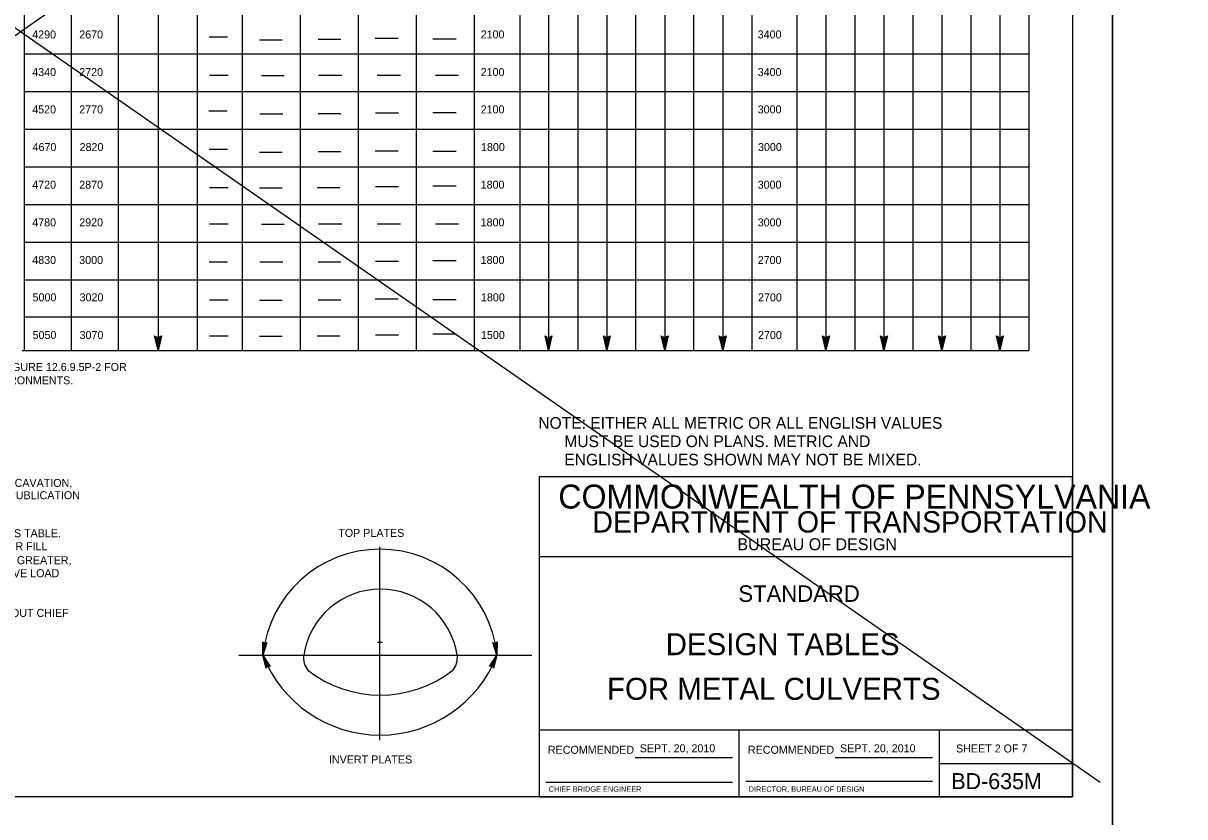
# Model space of a CAD drawing. Extents: x 591 to 2288, y -189 to 2187.
# Drawn here: x 1024 to 1459.5, y 1006.7 to 1304.4 of the extents above; entities that cross this region are included whole.
import ezdxf

# ---------------------------------------------------------------- set-up
doc = ezdxf.new("R2010")
doc.units = 0
for name, color, linetype in [('1', 7, 'Continuous'), ('2', 7, 'Continuous'), ('PLT-BNDY', 7, 'Continuous')]:
    doc.layers.add(name, color=color, linetype=linetype)

msp = doc.modelspace()

# ---------------------------------------------------------------- linework, layer by layer
at = {"layer": '1'}
for p, q in [((623.13, 1579.43), (1427.79, 1019.69)), ((1414.15, 1574.88), (614.04, 1015.14)), ((1292.34, 1014.21), (1292.34, 1039.21)), ((1367.34, 1039.21), (1367.34, 1014.21)), ((1253.43, 1028.93), (1289.84, 1028.93)), ((1328.43, 1028.93), (1364.84, 1028.93)), ((1219.84, 1019.71), (1289.84, 1019.71)), ((1294.84, 1020.09), (1364.84, 1020.09))]:
    msp.add_line(p, q, dxfattribs=at)
at = {"layer": '2'}
for p, q in [((1417.34, 1578.21), (1417.34, 1014.21)), ((1024.34, 1485.59), (1024.34, 1181.59)), ((1059.59, 1485.59), (1059.59, 1181.59)), ((1089.21, 1485.59), (1089.21, 1181.59)), ((1400.96, 1485.59), (1400.96, 1181.59)), ((1193.09, 1473.84), (1193.09, 1181.59)), ((1297.09, 1473.84), (1297.09, 1181.59)), ((1106.09, 1462.21), (1106.09, 1181.59)), ((1210.09, 1462.21), (1210.09, 1181.59)), ((1313.96, 1462.21), (1313.96, 1181.59)), ((1149.59, 1452.34), (1149.59, 1181.59)), ((1253.46, 1452.34), (1253.46, 1181.59)), ((1357.46, 1452.34), (1357.46, 1181.59)), ((1127.84, 1438.21), (1127.84, 1181.59)), ((1171.34, 1438.21), (1171.34, 1181.59)), ((1231.84, 1438.21), (1231.84, 1181.59)), ((1275.21, 1438.21), (1275.21, 1181.59)), ((1335.71, 1438.21), (1335.71, 1181.59)), ((1379.21, 1438.21), (1379.21, 1181.59)), ((1041.96, 1435.46), (1041.96, 1181.59)), ((1074.59, 1408.71), (1074.59, 1181.59)), ((1220.84, 1408.71), (1220.84, 1181.59)), ((1242.71, 1408.71), (1242.71, 1181.59)), ((1264.46, 1408.71), (1264.46, 1181.59)), ((1286.21, 1408.71), (1286.21, 1181.59)), ((1324.84, 1408.71), (1324.84, 1181.59)), ((1346.59, 1408.71), (1346.59, 1181.59)), ((1368.34, 1408.71), (1368.34, 1181.59)), ((1390.09, 1408.71), (1390.09, 1181.59)), ((1093.71, 1299.34), (1100.59, 1299.34)), ((1112.59, 1298.21), (1121.09, 1298.21)), ((1134.59, 1298.46), (1143.09, 1298.46)), ((1155.96, 1298.84), (1164.59, 1298.84)), ((1177.59, 1298.59), (1186.34, 1298.59)), ((1024.34, 1292.96), (1400.96, 1292.96)), ((1093.84, 1284.96), (1100.84, 1284.96)), ((1113.34, 1284.84), (1121.84, 1284.84)), ((1134.71, 1284.96), (1143.46, 1284.96)), ((1156.71, 1284.96), (1165.46, 1284.96)), ((1178.59, 1284.96), (1187.21, 1284.96)), ((1024.34, 1278.84), (1400.96, 1278.84)), ((1093.59, 1271.59), (1100.46, 1271.59)), ((1112.71, 1270.46), (1121.34, 1270.46)), ((1134.59, 1270.59), (1143.09, 1270.59)), ((1156.09, 1270.84), (1164.71, 1270.84)), ((1177.59, 1270.96), (1186.34, 1270.96)), ((1024.34, 1264.71), (1400.96, 1264.71)), ((1093.71, 1257.21), (1100.59, 1257.21)), ((1112.59, 1256.09), (1121.09, 1256.09)), ((1134.59, 1256.34), (1143.09, 1256.34)), ((1155.96, 1256.59), (1164.59, 1256.59)), ((1177.59, 1256.46), (1186.34, 1256.46)), ((1024.34, 1250.59), (1400.96, 1250.59)), ((1093.84, 1242.84), (1100.84, 1242.84)), ((1112.59, 1242.71), (1121.09, 1242.71)), ((1134.21, 1242.84), (1142.71, 1242.84)), ((1156.09, 1243.21), (1164.71, 1243.21)), ((1177.59, 1243.46), (1186.34, 1243.46)), ((1024.34, 1236.46), (1400.96, 1236.46)), ((1093.84, 1229.21), (1100.84, 1229.21)), ((1113.34, 1229.09), (1121.84, 1229.09)), ((1134.71, 1229.21), (1143.46, 1229.21)), ((1156.71, 1229.21), (1165.46, 1229.21)), ((1178.59, 1229.21), (1187.21, 1229.21)), ((1024.34, 1222.34), (1400.96, 1222.34)), ((1156.09, 1215.09), (1164.71, 1215.09)), ((1177.59, 1215.34), (1186.34, 1215.34)), ((1093.71, 1214.96), (1100.59, 1214.96)), ((1112.71, 1214.84), (1121.34, 1214.84)), ((1134.59, 1214.96), (1143.09, 1214.96)), ((1024.34, 1208.21), (1400.96, 1208.21)), ((1093.84, 1200.59), (1100.84, 1200.59)), ((1112.59, 1200.46), (1121.09, 1200.46)), ((1134.59, 1200.59), (1143.09, 1200.59)), ((1155.96, 1200.96), (1164.59, 1200.96)), ((1177.59, 1200.71), (1186.34, 1200.71)), ((1024.34, 1194.21), (1400.96, 1194.21)), ((1093.84, 1187.09), (1100.84, 1187.09)), ((1112.59, 1186.96), (1121.09, 1186.96)), ((1134.21, 1187.09), (1142.71, 1187.09)), ((1156.09, 1187.46), (1164.71, 1187.46)), ((1177.59, 1187.84), (1186.34, 1187.84)), ((1023.59, 1181.59), (1400.96, 1181.59)), ((1417.34, 1134.21), (1217.34, 1134.21)), ((1217.34, 1134.21), (1217.34, 1014.21)), ((1417.34, 1014.21), (1417.34, 1134.21)), ((1157.71, 1035.46), (1157.71, 1107.96)), ((1417.34, 1104.21), (1217.34, 1104.21)), ((1156.84, 1072.21), (1158.59, 1072.21)), ((1104.84, 1067.34), (1214.71, 1067.34)), ((1185.09, 1061.71), (1184.96, 1061.71)), ((1417.34, 1039.21), (1217.34, 1039.21)), ((1367.34, 1026.71), (1417.34, 1026.71)), ((1417.34, 1014.21), (631.34, 1014.21)), ((1217.34, 1014.21), (1417.34, 1014.21))]:
    msp.add_line(p, q, dxfattribs=at)
for points in [[(1075.46, 1186.84), (1074.96, 1186.59), (1074.59, 1181.59), (1075.46, 1186.84), (1075.84, 1187.09), (1074.59, 1181.59), (1074.21, 1186.59), (1073.59, 1186.71), (1074.59, 1181.59), (1073.21, 1187.09), (1073.59, 1186.71)], [(1221.96, 1186.84), (1221.34, 1186.59), (1220.84, 1181.59), (1221.96, 1186.84), (1222.21, 1187.09), (1220.84, 1181.59), (1220.46, 1186.59), (1220.09, 1186.71), (1220.84, 1181.59), (1219.71, 1187.09), (1220.09, 1186.71)], [(1243.71, 1186.84), (1243.09, 1186.59), (1242.71, 1181.59), (1243.71, 1186.84), (1243.96, 1187.09), (1242.71, 1181.59), (1242.34, 1186.59), (1241.71, 1186.71), (1242.71, 1181.59), (1241.46, 1187.09), (1241.71, 1186.71)], [(1265.34, 1186.84), (1264.84, 1186.59), (1264.46, 1181.59), (1265.34, 1186.84), (1265.71, 1187.09), (1264.46, 1181.59), (1264.09, 1186.59), (1263.46, 1186.71), (1264.46, 1181.59), (1263.09, 1187.09), (1263.46, 1186.71)], [(1287.09, 1186.84), (1286.59, 1186.59), (1286.21, 1181.59), (1287.09, 1186.84), (1287.46, 1187.09), (1286.21, 1181.59), (1285.84, 1186.59), (1285.21, 1186.71), (1286.21, 1181.59), (1284.84, 1187.09), (1285.21, 1186.71)], [(1325.84, 1186.84), (1325.21, 1186.59), (1324.84, 1181.59), (1325.84, 1186.84), (1326.21, 1187.09), (1324.84, 1181.59), (1324.46, 1186.59), (1323.96, 1186.71), (1324.84, 1181.59), (1323.59, 1187.09), (1323.96, 1186.71)], [(1347.59, 1186.84), (1346.96, 1186.59), (1346.59, 1181.59), (1347.59, 1186.84), (1347.96, 1187.09), (1346.59, 1181.59), (1346.21, 1186.59), (1345.71, 1186.71), (1346.59, 1181.59), (1345.34, 1187.09), (1345.71, 1186.71)], [(1369.34, 1186.84), (1368.71, 1186.59), (1368.34, 1181.59), (1369.34, 1186.84), (1369.71, 1187.09), (1368.34, 1181.59), (1367.96, 1186.59), (1367.34, 1186.71), (1368.34, 1181.59), (1367.09, 1187.09), (1367.34, 1186.71)], [(1391.09, 1186.84), (1390.59, 1186.59), (1390.09, 1181.59), (1391.09, 1186.84), (1391.34, 1187.09), (1390.09, 1181.59), (1389.71, 1186.59), (1389.09, 1186.71), (1390.09, 1181.59), (1388.84, 1187.09), (1389.09, 1186.71)], [(1115.09, 1071.84), (1114.71, 1071.71), (1113.84, 1067.34), (1115.09, 1071.84), (1115.34, 1072.09), (1113.84, 1067.34), (1114.34, 1071.84), (1113.96, 1072.09), (1113.84, 1067.34), (1113.84, 1072.34), (1113.96, 1072.09)], [(1201.46, 1072.09), (1201.21, 1071.84), (1201.59, 1067.34), (1201.46, 1072.09), (1201.71, 1072.34), (1201.59, 1067.34), (1200.71, 1071.71), (1200.34, 1071.84), (1201.59, 1067.34), (1200.09, 1072.09), (1200.34, 1071.84)], [(1115.21, 1062.84), (1115.46, 1063.09), (1113.84, 1067.34), (1115.21, 1062.84), (1115.09, 1062.46), (1113.84, 1067.34), (1115.84, 1063.34), (1116.21, 1063.21), (1113.84, 1067.34), (1116.59, 1063.09), (1116.21, 1063.21)], [(1199.09, 1063.21), (1199.46, 1063.34), (1201.59, 1067.34), (1199.09, 1063.21), (1198.84, 1063.09), (1201.59, 1067.34), (1199.96, 1063.09), (1200.21, 1062.84), (1201.59, 1067.34), (1200.34, 1062.46), (1200.21, 1062.84)]]:
    msp.add_lwpolyline(points, dxfattribs=at)
for centre, radius, start, end in [((1157.72, 1062.98), 44.11, 5.6241, 174.3759), ((1157.9, 1063.05), 29.07, 8.4323, 171.5893), ((1157.72, 1084.53), 47.16, 201.4219, 338.5781), ((1136.53, 1066.31), 7.46, 172.3667, 218.4979), ((1179.27, 1066.33), 7.46, 321.5021, 7.6333), ((1157.85, 1096.64), 44.27, 232.1732, 307.8489)]:
    msp.add_arc(centre, radius, start, end, dxfattribs=at)
at = {"layer": 'PLT-BNDY'}
for points in [[(591.34, 1593.21), (1432.34, 1593.21), (1432.34, 999.21), (591.34, 999.21)], [(1432.34, 1593.21), (2273.34, 1593.21), (2273.34, 999.21), (1432.34, 999.21)]]:
    msp.add_lwpolyline(points, close=True, dxfattribs=at)

# ---------------------------------------------------------------- texts
at = {"layer": '1'}
for s, height, p in [('RECOMMENDED', 3, (1220.67, 1030.34)), ('RECOMMENDED', 3, (1295.67, 1030.34)), ('CHIEF BRIDGE ENGINEER', 2.0003, (1220.93, 1016.09)), ('DIRECTOR, BUREAU OF DESIGN', 2.0003, (1295.94, 1016.09))]:
    msp.add_text(s, height=height, dxfattribs=at).set_placement(p)
at = {"layer": '2'}
for s, height, p in [('4290', 3, (1027.34, 1298.71)), ('2670', 3, (1044.96, 1298.71)), ('2100', 3, (1195.46, 1298.71)), ('3400', 3, (1299.34, 1298.71)), ('4340', 3, (1027.34, 1284.59)), ('2720', 3, (1044.96, 1284.59)), ('2100', 3, (1195.46, 1284.59)), ('3400', 3, (1299.34, 1284.59)), ('4520', 3, (1027.34, 1270.59)), ('2770', 3, (1044.96, 1270.59)), ('2100', 3, (1195.46, 1270.59)), ('3000', 3, (1299.34, 1270.59)), ('4670', 3, (1027.46, 1256.46)), ('2820', 3, (1045.09, 1256.46)), ('1800', 3, (1195.59, 1256.46)), ('3000', 3, (1299.46, 1256.46)), ('4720', 3, (1027.34, 1242.34)), ('2870', 3, (1044.96, 1242.34)), ('1800', 3, (1195.46, 1242.34)), ('3000', 3, (1299.34, 1242.34)), ('4780', 3, (1027.34, 1228.21)), ('2920', 3, (1044.96, 1228.21)), ('1800', 3, (1195.46, 1228.21)), ('3000', 3, (1299.34, 1228.21)), ('4830', 3, (1027.34, 1214.09)), ('3000', 3, (1044.96, 1214.09)), ('1800', 3, (1195.46, 1214.09)), ('2700', 3, (1299.34, 1214.09)), ('5000', 3, (1027.46, 1200.09)), ('3020', 3, (1045.09, 1200.09)), ('1800', 3, (1195.59, 1200.09)), ('2700', 3, (1299.46, 1200.09)), ('5050', 3, (1027.46, 1185.96)), ('3070', 3, (1045.09, 1185.96)), ('1500', 3, (1195.59, 1185.96)), ('2700', 3, (1299.46, 1185.96)), ('REFER TO DM4, FIGURE 12.6.9.5P-2 FOR', 3, (984.09, 1173.96)), ('CORROSIVE ENVIRONMENTS.', 3, (984.09, 1168.96)), ('NOTE: EITHER ALL METRIC OR ALL ENGLISH VALUES', 4.375, (1217.07, 1152.27)), ('      MUST BE USED ON PLANS. METRIC AND', 4.375, (1217.07, 1145.39)), ('      ENGLISH VALUES SHOWN MAY NOT BE MIXED.', 4.375, (1217.07, 1138.52)), ('7. THESE DESIGN VALUES ARE BASED UPON ASSUMPTION THAT THE EXCAVATION,', 3, (877.84, 1130.46)), ('BACKFILL AND CONSTRUCTION METHODS IN RC STANDARDS AND PUBLICATION', 3, (886.76, 1125.84)), ('COMMONWEALTH OF PENNSYLVANIA', 9, (1224.59, 1122.34)), ('DEPARTMENT OF TRANSPORTATION', 8.0002, (1237.34, 1113.34)), ('8. PIPE-ARCHES ARE DESIGNED FOR THE FILL HEIGHT INDICATED IN THIS TABLE.', 3, (877.83, 1111.59)), ('TOP PLATES', 3, (1142.09, 1111.71)), ('BUREAU OF DESIGN', 4.5, (1291.71, 1106.71)), ('IF LIVE LOAD NEEDS TO BE PERMITTED DURING CONSTRUCTION FOR FILL', 3, (886.16, 1106.71)), ('HEIGHT LESS THAN 2400 mm OR THE SPAN LENGTH, WHICHEVER IS GREATER,', 3, (886.72, 1101.46)), ('THE DESIGN OF THE TOP PLATE MUST BE CHECKED FOR WORST LIVE LOAD', 3, (886.82, 1096.59)), ('STANDARD', 6.188, (1292.09, 1087.34)), ('9. PIPE MAY NOT BE PLACED WITHIN THE PAVEMENT STRUCTURE WITHOUT CHIEF', 3, (877.83, 1081.69)), ('DESIGN TABLES', 8.2515, (1264.84, 1067.34)), ('FOR METAL CULVERTS', 8.2515, (1242.84, 1050.59)), ('SEPT. 20, 2010', 3, (1255.1, 1030.91)), ('SHEET 2 OF 7', 3, (1373.71, 1030.84)), ('INVERT PLATES', 3, (1138.59, 1026.71)), ('BD-635M', 6, (1371.96, 1017.09))]:
    msp.add_text(s, height=height, dxfattribs=at).set_placement(p)
msp.add_text('SEPT. 20, 2010', height=3, rotation=360, dxfattribs=at).set_placement((1330.2, 1030.91))

doc.saveas('drawing.dxf')
